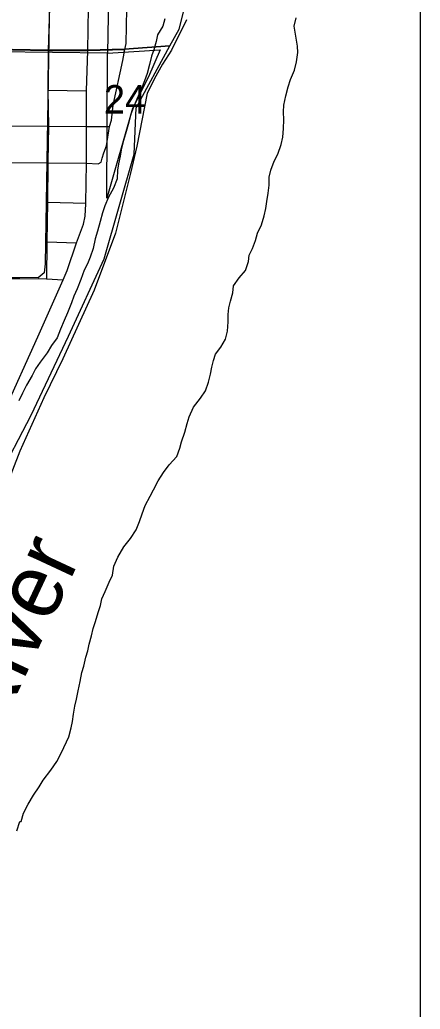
# Model space of a CAD drawing. Extents: x 2.1 to 8.9, y 14.1 to 20.9.
# Drawn here: x 8.311 to 8.9, y 17.687 to 19.144 of the extents above; entities that cross this region are included whole.
import ezdxf

# ---------------------------------------------------------------- set-up
doc = ezdxf.new("R2010")
doc.units = 0
for name, color, linetype in [('Default', 7, 'Continuous'), ('GM_X_County_Road_Text', 7, 'Continuous'), ('GM_X_Interchange_Ramps', 7, 'Continuous'), ('GM_X_State_Location', 7, 'Continuous'), ('GM_X_State_Shield', 7, 'Continuous'), ('GM_X_Township_Road', 7, 'Continuous'), ('GM_X_Unincorporated_Location', 7, 'Continuous'), ('GM_X_Unincorporated_Text', 7, 'Continuous'), ('SC_Shading1', 7, 'Continuous'), ('SH_Cut_Line', 7, 'Continuous'), ('SH_Data', 7, 'Continuous')]:
    doc.layers.add(name, color=color, linetype=linetype)

msp = doc.modelspace()

# ---------------------------------------------------------------- linework, layer by layer
at = {"layer": 'Default'}
for p, q in [((8.5453, 19.1308), (8.5605, 19.1918)), ((8.5318, 19.1061), (8.5453, 19.1308)), ((8.3526, 19.0999), (8.2997, 19.1005)), ((8.2997, 19.1005), (8.3526, 19.0999)), ((8.411, 19.0996), (8.3526, 19.0999)), ((8.3526, 19.0999), (8.411, 19.0996)), ((8.465, 19.1014), (8.411, 19.0996)), ((8.411, 19.0996), (8.465, 19.1014)), ((8.5318, 19.1061), (8.465, 19.1014)), ((8.465, 19.1014), (8.5318, 19.1061)), ((8.4822, 19.0147), (8.5318, 19.1061)), ((8.479, 18.9465), (8.4822, 19.0147)), ((8.435, 18.7926), (8.479, 18.9465)), ((8.3826, 18.6786), (8.435, 18.7926)), ((8.3275, 18.5623), (8.3826, 18.6786)), ((8.2682, 18.4486), (8.3275, 18.5623))]:
    msp.add_line(p, q, dxfattribs=at)
at = {"layer": 'GM_X_Interchange_Ramps'}
for p, q in [((8.4603, 20.0986), (8.4398, 19.0954)), ((8.4398, 19.0954), (7.4585, 19.1081)), ((8.4391, 18.8816), (8.4398, 19.0954)), ((8.4398, 19.0954), (8.5174, 19.1001)), ((8.5174, 19.1001), (8.5002, 19.0607)), ((8.5002, 19.0607), (8.4766, 19.0136)), ((8.4766, 19.0136), (8.4391, 18.8816))]:
    msp.add_line(p, q, dxfattribs=at)
at = {"layer": 'GM_X_State_Location'}
for p, q in [((8.5243, 19.1458), (8.5214, 19.1351)), ((8.7147, 19.135), (8.7175, 19.1472)), ((8.5137, 19.1221), (8.5113, 19.1125)), ((8.5214, 19.1351), (8.5137, 19.1221)), ((8.7172, 19.1206), (8.7147, 19.135)), ((8.5113, 19.1125), (8.5081, 19.1003)), ((8.7194, 19.1058), (8.7172, 19.1206)), ((8.5081, 19.1003), (8.5045, 19.0908)), ((8.718, 19.0827), (8.72, 19.0964)), ((8.72, 19.0964), (8.7194, 19.1058)), ((8.5017, 19.0786), (8.4981, 19.0656)), ((8.5045, 19.0908), (8.5017, 19.0786)), ((8.7152, 19.0705), (8.718, 19.0827)), ((8.4981, 19.0656), (8.4942, 19.0546)), ((8.709, 19.0563), (8.7152, 19.0705)), ((8.4942, 19.0546), (8.4888, 19.0408)), ((8.7058, 19.0456), (8.709, 19.0563)), ((8.4888, 19.0408), (8.4829, 19.0278)), ((8.7022, 19.0327), (8.7058, 19.0456)), ((8.4829, 19.0278), (8.4782, 19.0159)), ((8.6995, 19.0186), (8.7022, 19.0327)), ((8.4782, 19.0159), (8.4739, 19.0041)), ((8.6989, 19.0087), (8.6995, 19.0186)), ((8.6995, 18.997), (8.6989, 19.0087)), ((8.4715, 18.9938), (8.4676, 18.9801)), ((8.4739, 19.0041), (8.4715, 18.9938)), ((8.699, 18.9844), (8.6995, 18.997)), ((8.4676, 18.9801), (8.4633, 18.9667)), ((8.6981, 18.9715), (8.699, 18.9844)), ((8.4633, 18.9667), (8.4605, 18.9553)), ((8.6953, 18.9608), (8.6981, 18.9715)), ((8.4605, 18.9553), (8.4584, 18.9435)), ((8.6903, 18.9467), (8.6953, 18.9608)), ((8.456, 18.9324), (8.4546, 18.9229)), ((8.4584, 18.9435), (8.456, 18.9324)), ((8.6801, 18.923), (8.6851, 18.9364)), ((8.6851, 18.9364), (8.6903, 18.9467)), ((8.4546, 18.9229), (8.4541, 18.91)), ((8.678, 18.9127), (8.6801, 18.923)), ((8.4541, 18.91), (8.4487, 18.8966)), ((8.6779, 18.9009), (8.678, 18.9127)), ((8.4487, 18.8966), (8.4414, 18.8832)), ((8.6742, 18.8766), (8.6762, 18.8891)), ((8.6762, 18.8891), (8.6779, 18.9009)), ((8.4414, 18.8832), (8.4359, 18.8702)), ((8.6729, 18.8663), (8.6742, 18.8766)), ((8.4324, 18.8599), (8.4292, 18.8473)), ((8.4359, 18.8702), (8.4324, 18.8599)), ((8.6704, 18.8556), (8.6729, 18.8663)), ((8.4292, 18.8473), (8.4253, 18.8332)), ((8.6665, 18.8423), (8.6704, 18.8556)), ((8.4253, 18.8332), (8.4217, 18.8217)), ((8.6607, 18.83), (8.6665, 18.8423)), ((8.4217, 18.8217), (8.4186, 18.8076)), ((8.6531, 18.8075), (8.6578, 18.8194)), ((8.6578, 18.8194), (8.6607, 18.83)), ((8.4186, 18.8076), (8.4143, 18.795)), ((8.6484, 18.7979), (8.6531, 18.8075)), ((8.4143, 18.795), (8.4107, 18.7851)), ((8.6431, 18.7751), (8.6474, 18.7884)), ((8.6474, 18.7884), (8.6484, 18.7979)), ((8.4056, 18.7755), (8.4009, 18.7618)), ((8.4107, 18.7851), (8.4056, 18.7755)), ((8.6335, 18.7646), (8.6431, 18.7751)), ((8.4009, 18.7618), (8.3955, 18.748)), ((8.6254, 18.7527), (8.6335, 18.7646)), ((8.3955, 18.748), (8.3904, 18.7373)), ((8.6241, 18.7425), (8.6254, 18.7527)), ((8.3904, 18.7373), (8.3868, 18.7274)), ((8.6184, 18.7203), (8.6209, 18.7299)), ((8.6209, 18.7299), (8.6241, 18.7425)), ((8.3868, 18.7274), (8.381, 18.7128)), ((8.6175, 18.7105), (8.6184, 18.7203)), ((8.3763, 18.7017), (8.3708, 18.6887)), ((8.381, 18.7128), (8.3763, 18.7017)), ((8.6164, 18.6858), (8.6173, 18.6994)), ((8.6173, 18.6994), (8.6175, 18.7105)), ((8.3708, 18.6887), (8.3658, 18.6761)), ((8.6136, 18.6739), (8.6164, 18.6858)), ((8.3658, 18.6761), (8.3573, 18.6649)), ((8.6067, 18.6621), (8.6136, 18.6739)), ((8.3573, 18.6649), (8.351, 18.6538)), ((8.5989, 18.652), (8.6067, 18.6621)), ((8.351, 18.6538), (8.3407, 18.64)), ((8.5936, 18.6326), (8.596, 18.6425)), ((8.596, 18.6425), (8.5989, 18.652)), ((8.3341, 18.6304), (8.3289, 18.6204)), ((8.3407, 18.64), (8.3341, 18.6304)), ((8.5915, 18.6227), (8.5936, 18.6326)), ((8.3289, 18.6204), (8.3209, 18.6062)), ((8.5887, 18.6105), (8.5915, 18.6227)), ((8.3209, 18.6062), (8.3147, 18.5943)), ((8.5766, 18.5871), (8.584, 18.5979)), ((8.584, 18.5979), (8.5887, 18.6105)), ((8.3147, 18.5943), (8.3092, 18.5832)), ((8.5663, 18.574), (8.5766, 18.5871)), ((8.5601, 18.5595), (8.5663, 18.574)), ((8.5573, 18.5499), (8.5601, 18.5595)), ((8.5537, 18.537), (8.5573, 18.5499)), ((8.5487, 18.5228), (8.5537, 18.537)), ((8.5419, 18.5011), (8.5462, 18.5133)), ((8.5462, 18.5133), (8.5487, 18.5228)), ((8.5304, 18.4891), (8.5419, 18.5011)), ((8.5223, 18.4775), (8.5304, 18.4891)), ((8.5145, 18.4656), (8.5223, 18.4775)), ((8.5028, 18.4426), (8.5076, 18.4522)), ((8.5076, 18.4522), (8.5145, 18.4656)), ((8.4955, 18.4292), (8.5028, 18.4426)), ((8.4908, 18.4166), (8.4955, 18.4292)), ((8.4869, 18.4055), (8.4908, 18.4166)), ((8.4737, 18.3802), (8.4822, 18.3933)), ((8.4822, 18.3933), (8.4869, 18.4055)), ((8.4641, 18.3679), (8.4737, 18.3802)), ((8.4553, 18.3529), (8.4641, 18.3679)), ((8.4491, 18.3395), (8.4553, 18.3529)), ((8.4471, 18.3266), (8.4491, 18.3395)), ((8.4423, 18.3159), (8.4471, 18.3266)), ((8.4365, 18.3025), (8.4423, 18.3159)), ((8.4294, 18.2818), (8.4318, 18.2914)), ((8.4318, 18.2914), (8.4365, 18.3025)), ((8.4261, 18.2715), (8.4294, 18.2818)), ((8.4222, 18.2582), (8.4261, 18.2715)), ((8.4162, 18.2368), (8.419, 18.2478)), ((8.419, 18.2478), (8.4222, 18.2582)), ((8.413, 18.2246), (8.4162, 18.2368)), ((8.4109, 18.215), (8.413, 18.2246)), ((8.4049, 18.1925), (8.4081, 18.2055)), ((8.4081, 18.2055), (8.4109, 18.215)), ((8.402, 18.183), (8.4049, 18.1925)), ((8.3996, 18.17), (8.402, 18.183)), ((8.3965, 18.1559), (8.3996, 18.17)), ((8.3941, 18.1437), (8.3965, 18.1559)), ((8.3899, 18.1216), (8.392, 18.1334)), ((8.392, 18.1334), (8.3941, 18.1437)), ((8.3886, 18.111), (8.3899, 18.1216)), ((8.3865, 18.1014), (8.3886, 18.111)), ((8.3721, 18.0651), (8.383, 18.0881)), ((8.383, 18.0881), (8.3865, 18.1014)), ((8.3655, 18.052), (8.3721, 18.0651)), ((8.3566, 18.039), (8.3655, 18.052)), ((8.3452, 18.0243), (8.3566, 18.039)), ((8.3312, 18.0024), (8.3393, 18.0147)), ((8.3393, 18.0147), (8.3452, 18.0243)), ((8.3231, 17.9893), (8.3312, 18.0024)), ((8.3165, 17.9756), (8.3231, 17.9893)), ((8.313, 17.9637), (8.3165, 17.9756)), ((8.3064, 17.9499), (8.3111, 17.9637)), ((8.3111, 17.9637), (8.313, 17.9637))]:
    msp.add_line(p, q, dxfattribs=at)
at = {"layer": 'GM_X_State_Shield'}
for p, q in [((8.3546, 19.1628), (8.3528, 19.0994)), ((8.4112, 19.0991), (8.4117, 19.1623)), ((8.2999, 19.1), (8.3528, 19.0994)), ((8.3528, 19.0994), (8.3523, 19.0408)), ((8.3528, 19.0994), (8.4112, 19.0991)), ((8.4091, 19.0398), (8.4112, 19.0991)), ((8.3523, 19.0408), (8.353, 18.9879)), ((8.4088, 18.9871), (8.4091, 19.0398)), ((8.353, 18.9879), (8.352, 18.9359)), ((8.4091, 18.9332), (8.4088, 18.9871)), ((8.352, 18.9339), (8.3515, 18.8758)), ((8.352, 18.9359), (8.352, 18.9339)), ((8.408, 18.8745), (8.4091, 18.9332)), ((8.3515, 18.8758), (8.3504, 18.8172)), ((8.408, 18.8735), (8.408, 18.8745)), ((8.407, 18.855), (8.408, 18.8735)), ((8.4047, 18.8432), (8.407, 18.855)), ((8.3945, 18.8159), (8.4047, 18.8432)), ((8.3504, 18.8172), (8.3502, 18.763)), ((8.3804, 18.7752), (8.3945, 18.8159)), ((8.3747, 18.7614), (8.3804, 18.7752)), ((8.2329, 18.7641), (8.3111, 18.7633)), ((8.3111, 18.7633), (8.3502, 18.763)), ((8.3502, 18.763), (8.3747, 18.7614))]:
    msp.add_line(p, q, dxfattribs=at)
at = {"layer": 'GM_X_Township_Road'}
for p, q in [((8.556, 19.1446), (8.5343, 19.0998)), ((8.5343, 19.0998), (8.521, 19.0789)), ((8.521, 19.0789), (8.511, 19.0615)), ((8.511, 19.0615), (8.4985, 19.0364)), ((8.4985, 19.0364), (8.4833, 18.9584)), ((8.4833, 18.9584), (8.4736, 18.9186)), ((8.4736, 18.9186), (8.4515, 18.8302)), ((8.4515, 18.8302), (8.4205, 18.746)), ((8.4205, 18.746), (8.3741, 18.645)), ((8.3741, 18.645), (8.3461, 18.5875)), ((8.3461, 18.5875), (8.3111, 18.5089)), ((8.3111, 18.5089), (8.2891, 18.4531))]:
    msp.add_line(p, q, dxfattribs=at)
at = {"layer": 'GM_X_Unincorporated_Text'}
for p, q in [((8.4675, 19.1097), (8.4683, 19.1608)), ((8.4652, 19.1009), (8.4675, 19.1097)), ((8.4112, 19.0991), (8.4652, 19.1009)), ((8.4625, 19.0844), (8.4652, 19.1009)), ((8.4484, 19.0189), (8.4625, 19.0844)), ((8.3523, 19.0408), (8.4091, 19.0398)), ((8.4456, 18.9968), (8.4484, 19.0189)), ((8.4427, 18.9871), (8.4456, 18.9968)), ((8.2917, 18.9885), (8.353, 18.9879)), ((8.353, 18.9879), (8.4088, 18.9871)), ((8.4088, 18.9871), (8.4427, 18.9871)), ((8.4383, 18.9587), (8.4427, 18.9871)), ((8.432, 18.9407), (8.4344, 18.9483)), ((8.4344, 18.9483), (8.4383, 18.9587)), ((8.2834, 18.9343), (8.352, 18.9339)), ((8.352, 18.9339), (8.4091, 18.9332)), ((8.4091, 18.9332), (8.426, 18.9324)), ((8.426, 18.9324), (8.4305, 18.935)), ((8.4305, 18.935), (8.432, 18.9407)), ((8.3515, 18.8758), (8.408, 18.8745)), ((8.3504, 18.8172), (8.3945, 18.8159)), ((8.3375, 18.6773), (8.3747, 18.7614)), ((8.288, 18.5677), (8.3375, 18.6773))]:
    msp.add_line(p, q, dxfattribs=at)
at = {"layer": 'SC_Shading1'}
for p, q in [((8.3573, 19.356), (8.3483, 18.7848)), ((8.3466, 18.7719), (8.3381, 18.7645)), ((8.3483, 18.7848), (8.3466, 18.7719)), ((8.3381, 18.7645), (8.2533, 18.7651))]:
    msp.add_line(p, q, dxfattribs=at)
at = {"layer": 'SH_Cut_Line'}
for p, q in [((8.5453, 19.1308), (8.5605, 19.1918)), ((8.5318, 19.1061), (8.5453, 19.1308)), ((8.4822, 19.0147), (8.5318, 19.1061)), ((8.479, 18.9465), (8.4822, 19.0147)), ((8.435, 18.7926), (8.479, 18.9465)), ((8.3826, 18.6786), (8.435, 18.7926)), ((8.3275, 18.5623), (8.3826, 18.6786)), ((8.2682, 18.4486), (8.3275, 18.5623))]:
    msp.add_line(p, q, dxfattribs=at)
at = {"layer": 'SH_Data'}
msp.add_line((8.9, 20.9), (8.9, 14.1), dxfattribs=at)
msp.add_line((8.9, 20.9), (8.9, 14.1), dxfattribs=at)

# ---------------------------------------------------------------- texts
at = {"layer": 'GM_X_County_Road_Text'}
msp.add_text('24', height=0.04186, rotation=0, dxfattribs=at).set_placement((8.4346, 19.0064))
at = {"layer": 'GM_X_Unincorporated_Location'}
msp.add_text('River', height=0.09475, rotation=64.959, dxfattribs=at).set_placement((8.2771, 18.0874))

doc.saveas('drawing.dxf')
